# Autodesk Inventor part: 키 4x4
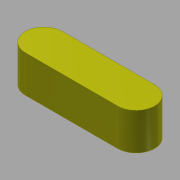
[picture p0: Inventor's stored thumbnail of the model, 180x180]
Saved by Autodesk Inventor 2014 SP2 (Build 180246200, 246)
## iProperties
Created: 2014-10
Part Number: 키 4x4
Document SubType Name: Modeling
Designer: KYOUNG IL JANG
Density: 7.86 g/cm^3
Mass: 1.65269 g
Surface Area: 2.35398 cm^2
Volume: 0.210265 cm^3
Material: 강철, 연강
Appearance: 노란색
Author: SeoGD™ [www.esajin.kr]
Revision Number: 1
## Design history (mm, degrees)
sketch "스케치1"
  geometry: L1 (-5, -2)-(5, -2); L2 (5, 2)-(-5, 2); A1 r 2 centre (5, 0) between (5, -2) and (5, 2); A2 r 2 centre (-5, 0) between (-5, 2) and (-5, -2); 2 further points
  constraints: 4 end point, 4 point on circle, 4 tangent, 2 centre point, 1 horizontal, 1 horizontal alignment, 1 midpoint, 1 parallel, 1 vertical alignment
  dimensions: "d0" = 4 distance between parallel lines of L1 L2; "d1" = 14 dimension on A1 A2
extrude "돌출1" new body sketch "스케치1" stored distance "d2" = 4; taper "d3" = 0 deg
node "솔리드1"
